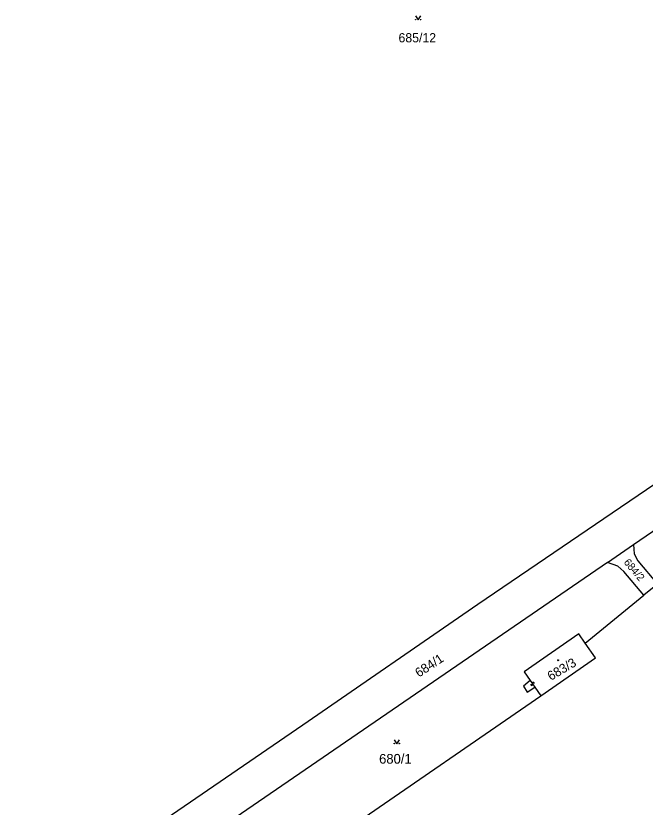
# Model space of a CAD drawing. Extents: x -600391 to -599491, y -1160176 to -1159402.
# Drawn here: x -599908.7 to -599792.2, y -1159833.2 to -1159686.6 of the extents above; entities that cross this region are included whole.
import ezdxf

# ---------------------------------------------------------------- set-up
doc = ezdxf.new("R2010")
doc.units = 0
for name, color, linetype in [('Level 1', 7, 'Continuous'), ('Level 13', 7, 'Continuous'), ('Level 3', 7, 'Continuous'), ('Level 4', 7, 'Continuous'), ('Level 5', 7, 'Continuous')]:
    doc.layers.add(name, color=color, linetype=linetype)

msp = doc.modelspace()

# ---------------------------------------------------------------- linework, layer by layer
at = {"layer": 'Level 1'}
for points in [[(-599768.64, -1159758.53), (-599823.19, -1159795.64), (-599855.6, -1159818.02), (-599902.81, -1159850.42), (-599908.7, -1159854.48)], [(-599794.35, -1159784.57), (-599779.15, -1159774.14)], [(-599799.17, -1159787.88), (-599794.35, -1159784.57)], [(-599794.35, -1159784.57), (-599794.24, -1159786.26), (-599793.56, -1159787.6), (-599789.93, -1159791.92)], [(-599799.17, -1159787.88), (-599875.57, -1159840.32)], [(-599792.44, -1159793.96), (-599796.15, -1159789.55), (-599797.25, -1159788.53), (-599799.17, -1159787.88)], [(-599789.93, -1159791.92), (-599792.44, -1159793.96)], [(-599803.32, -1159802.8), (-599792.44, -1159793.96)], [(-599803.32, -1159802.8), (-599804.52, -1159801.11), (-599814.63, -1159808.15), (-599813.5, -1159809.76)], [(-599811.52, -1159812.6), (-599801.4, -1159805.52), (-599803.32, -1159802.8)], [(-599813.5, -1159809.76), (-599814.73, -1159810.76), (-599814.04, -1159811.92), (-599812.66, -1159810.97)], [(-599812.66, -1159810.97), (-599811.52, -1159812.6)], [(-599826.2, -1159851.6), (-599827.97, -1159850.26), (-599846.98, -1159837.04), (-599811.52, -1159812.6)]]:
    msp.add_lwpolyline(points, dxfattribs=at)
at = {"layer": 'Level 13'}
for centre, start, end in [((-599813.23, -1159810.46), 161.9272, 34.5172), ((-599812.93, -1159810.26), 342.1417, 214.2397)]:
    msp.add_arc(centre, 0.184, start, end, dxfattribs=at)
at = {"layer": 'Level 3'}
msp.add_lwpolyline([(-599813.5, -1159809.76), (-599812.66, -1159810.97)], dxfattribs=at)
at = {"layer": 'Level 5'}
for points in [[(-599834.74, -1159686.64), (-599834.24, -1159687.39), (-599833.74, -1159686.64)], [(-599838.69, -1159820.7), (-599838.19, -1159821.45), (-599837.69, -1159820.7)]]:
    msp.add_lwpolyline(points, dxfattribs=at)
for centre, radius in [((-599834.69, -1159687.34), 0.05), ((-599833.79, -1159687.34), 0.05), ((-599808.34, -1159805.98), 0.09), ((-599808.34, -1159805.98), 0.0521), ((-599838.64, -1159821.4), 0.05), ((-599837.74, -1159821.4), 0.05)]:
    msp.add_circle(centre, radius, dxfattribs=at)

# ---------------------------------------------------------------- texts
at = {"layer": 'Level 4'}
for s, height, p in [('685/12', 1.7, (-599837.87, -1159691.55)), ('680/1', 1.8, (-599841.46, -1159825.14))]:
    msp.add_text(s, height=height, dxfattribs=at).set_placement(p)
for s, height, rotation, p in [('684/2', 1.4, 310.0729, (-599796.27, -1159787.9)), ('684/1', 1.7, 33.3, (-599834.1, -1159809.21)), ('683/3', 1.7, 30.7817, (-599809.67, -1159809.82))]:
    msp.add_text(s, height=height, rotation=rotation, dxfattribs=at).set_placement(p)

doc.saveas('drawing.dxf')
